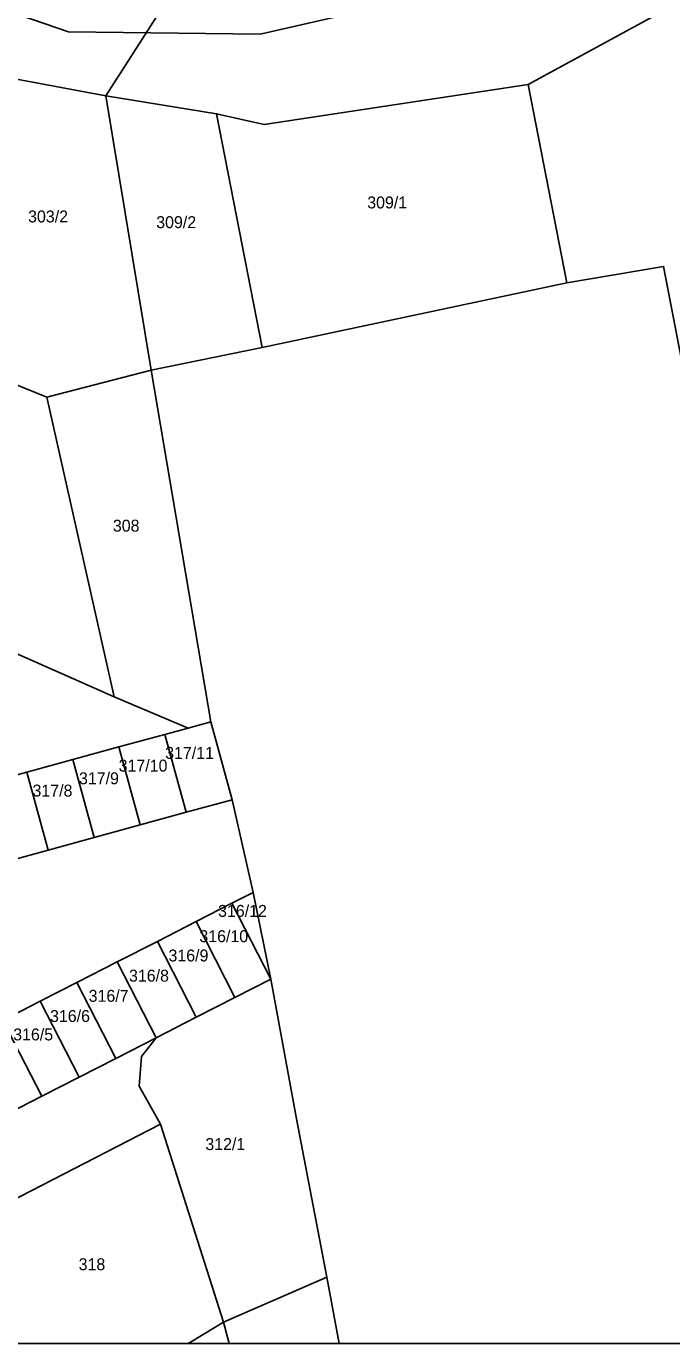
# Model space of a CAD drawing. Extents: x -873642 to -872917, y -1012962 to -1012567.
# Drawn here: x -873527.3 to -873481.3, y -1012961.7 to -1012867.8 of the extents above; entities that cross this region are included whole.
import ezdxf

# ---------------------------------------------------------------- set-up
doc = ezdxf.new("R2010")
doc.units = 0
for name, color, linetype in [('cisla_parcelni_kn', 7, 'Continuous'), ('osy_ulic', 7, 'Continuous'), ('parcely_kn', 7, 'Continuous'), ('stavebni_objekty_ostatni', 7, 'Continuous')]:
    doc.layers.add(name, color=color, linetype=linetype)

msp = doc.modelspace()

# ---------------------------------------------------------------- linework, layer by layer
at = {"layer": 'osy_ulic'}
msp.add_lwpolyline([(-873411.85, -1012822.53), (-873495.73, -1012864.97), (-873510.64, -1012868.38), (-873524.3, -1012868.21), (-873541.44, -1012862.33)], dxfattribs=at)
at = {"layer": 'parcely_kn'}
for p, q in [((-873528.799, -1012961.688), (-873515.787, -1012961.688)), ((-873528.799, -1012961.688), (-873515.787, -1012961.688)), ((-873515.787, -1012961.688), (-873512.858, -1012961.688)), ((-873515.787, -1012961.688), (-873512.858, -1012961.688)), ((-873512.858, -1012961.688), (-873505.023, -1012961.688)), ((-873512.858, -1012961.688), (-873505.023, -1012961.688)), ((-873505.023, -1012961.688), (-873433.111, -1012961.688)), ((-873505.023, -1012961.688), (-873433.111, -1012961.688))]:
    msp.add_line(p, q, dxfattribs=at)
for points in [[(-873407.44, -1012826.19), (-873491.56, -1012871.97), (-873510.35, -1012874.83), (-873513.75, -1012874.06), (-873521.64, -1012872.77), (-873517.87, -1012866.9), (-873506.6, -1012864.53), (-873501.14, -1012863.39), (-873495.55, -1012861.22), (-873491.75, -1012859.41), (-873424.19, -1012825.53), (-873422.58, -1012824.33), (-873421.37, -1012822.77), (-873420.24, -1012820.89), (-873420.07, -1012818.95), (-873420.2, -1012816.99), (-873420.81, -1012815.05)], [(-873407.44, -1012826.19), (-873491.56, -1012871.97), (-873510.35, -1012874.83), (-873513.75, -1012874.06), (-873521.64, -1012872.77), (-873517.87, -1012866.9), (-873506.6, -1012864.53), (-873501.14, -1012863.39), (-873495.55, -1012861.22), (-873491.75, -1012859.41), (-873424.19, -1012825.53), (-873422.58, -1012824.33), (-873421.37, -1012822.77), (-873420.24, -1012820.89), (-873420.07, -1012818.95), (-873420.2, -1012816.99), (-873420.81, -1012815.05)], [(-873518.4, -1012892.32), (-873525.83, -1012894.25), (-873533.05, -1012891.32), (-873548.33, -1012885.12), (-873544.35, -1012876.78), (-873540.91, -1012872.09), (-873537.72, -1012870.46), (-873532.98, -1012870.67), (-873521.64, -1012872.77)], [(-873518.4, -1012892.32), (-873525.83, -1012894.25), (-873533.05, -1012891.32), (-873548.33, -1012885.12), (-873544.35, -1012876.78), (-873540.91, -1012872.09), (-873537.72, -1012870.46), (-873532.98, -1012870.67), (-873521.64, -1012872.77)], [(-873513.75, -1012874.06), (-873510.35, -1012874.83), (-873491.56, -1012871.97), (-873488.8, -1012886.1), (-873510.5, -1012890.72)], [(-873513.75, -1012874.06), (-873510.35, -1012874.83), (-873491.56, -1012871.97), (-873488.8, -1012886.1), (-873510.5, -1012890.72)], [(-873510.5, -1012890.72), (-873518.4, -1012892.32), (-873521.64, -1012872.77), (-873513.75, -1012874.06)], [(-873510.5, -1012890.72), (-873518.4, -1012892.32), (-873521.64, -1012872.77), (-873513.75, -1012874.06)], [(-873533.05, -1012891.32), (-873525.83, -1012894.25), (-873521.05, -1012915.61), (-873532.64, -1012910.47), (-873539.95, -1012907.22)], [(-873533.05, -1012891.32), (-873525.83, -1012894.25), (-873521.05, -1012915.61), (-873532.64, -1012910.47), (-873539.95, -1012907.22)], [(-873518.4, -1012892.32), (-873514.15, -1012917.38), (-873515.78, -1012917.83), (-873521.05, -1012915.61), (-873525.83, -1012894.25)], [(-873518.4, -1012892.32), (-873514.15, -1012917.38), (-873515.78, -1012917.83), (-873521.05, -1012915.61), (-873525.83, -1012894.25)], [(-873517.43, -1012918.28), (-873515.78, -1012917.83), (-873514.15, -1012917.38), (-873512.63, -1012922.93), (-873515.91, -1012923.83)], [(-873517.43, -1012918.28), (-873515.78, -1012917.83), (-873514.15, -1012917.38), (-873512.63, -1012922.93), (-873515.91, -1012923.83)], [(-873520.71, -1012919.17), (-873517.43, -1012918.28), (-873515.91, -1012923.83), (-873519.19, -1012924.73)], [(-873520.71, -1012919.17), (-873517.43, -1012918.28), (-873515.91, -1012923.83), (-873519.19, -1012924.73)], [(-873523.99, -1012920.07), (-873520.71, -1012919.17), (-873519.19, -1012924.73), (-873522.47, -1012925.63)], [(-873523.99, -1012920.07), (-873520.71, -1012919.17), (-873519.19, -1012924.73), (-873522.47, -1012925.63)], [(-873527.27, -1012920.96), (-873523.99, -1012920.07), (-873522.47, -1012925.63), (-873525.75, -1012926.52)], [(-873527.27, -1012920.96), (-873523.99, -1012920.07), (-873522.47, -1012925.63), (-873525.75, -1012926.52)], [(-873530.55, -1012921.86), (-873527.27, -1012920.96), (-873525.75, -1012926.52), (-873529.03, -1012927.43)], [(-873530.55, -1012921.86), (-873527.27, -1012920.96), (-873525.75, -1012926.52), (-873529.03, -1012927.43)], [(-873512.65, -1012930.31), (-873511.15, -1012929.54), (-873509.89, -1012935.71)], [(-873512.65, -1012930.31), (-873511.15, -1012929.54), (-873509.89, -1012935.71)], [(-873512.65, -1012930.31), (-873509.89, -1012935.71), (-873512.45, -1012937.02), (-873515.21, -1012931.62)], [(-873512.65, -1012930.31), (-873509.89, -1012935.71), (-873512.45, -1012937.02), (-873515.21, -1012931.62)], [(-873512.45, -1012937.02), (-873515.2, -1012938.43), (-873517.96, -1012933.03), (-873515.21, -1012931.62)], [(-873512.45, -1012937.02), (-873515.2, -1012938.43), (-873517.96, -1012933.03), (-873515.21, -1012931.62)], [(-873515.2, -1012938.43), (-873518.06, -1012939.89), (-873520.82, -1012934.49), (-873517.96, -1012933.03)], [(-873515.2, -1012938.43), (-873518.06, -1012939.89), (-873520.82, -1012934.49), (-873517.96, -1012933.03)], [(-873518.06, -1012939.89), (-873520.92, -1012941.36), (-873523.69, -1012935.96), (-873520.82, -1012934.49)], [(-873518.06, -1012939.89), (-873520.92, -1012941.36), (-873523.69, -1012935.96), (-873520.82, -1012934.49)], [(-873520.92, -1012941.36), (-873523.53, -1012942.7), (-873526.3, -1012937.29), (-873523.69, -1012935.96)], [(-873520.92, -1012941.36), (-873523.53, -1012942.7), (-873526.3, -1012937.29), (-873523.69, -1012935.96)], [(-873512.45, -1012937.02), (-873509.89, -1012935.71), (-873508.05, -1012945.66), (-873505.9, -1012956.95), (-873513.26, -1012960.15), (-873517.74, -1012946.06), (-873519.25, -1012943.34), (-873519.1, -1012941.22), (-873518.06, -1012939.89), (-873515.2, -1012938.43)], [(-873512.45, -1012937.02), (-873509.89, -1012935.71), (-873508.05, -1012945.66), (-873505.9, -1012956.95), (-873513.26, -1012960.15), (-873517.74, -1012946.06), (-873519.25, -1012943.34), (-873519.1, -1012941.22), (-873518.06, -1012939.89), (-873515.2, -1012938.43)], [(-873523.53, -1012942.7), (-873526.2, -1012944.06), (-873528.97, -1012938.66), (-873526.3, -1012937.29)], [(-873523.53, -1012942.7), (-873526.2, -1012944.06), (-873528.97, -1012938.66), (-873526.3, -1012937.29)], [(-873526.2, -1012944.06), (-873529.35, -1012945.67), (-873532.12, -1012940.27), (-873528.97, -1012938.66)], [(-873526.2, -1012944.06), (-873529.35, -1012945.67), (-873532.12, -1012940.27), (-873528.97, -1012938.66)]]:
    msp.add_lwpolyline(points, close=True, dxfattribs=at)
for points in [[(-873478.14, -1012904.47), (-873481.91, -1012884.93), (-873488.8, -1012886.1), (-873491.56, -1012871.97), (-873407.44, -1012826.19)], [(-873478.14, -1012904.47), (-873481.91, -1012884.93), (-873488.8, -1012886.1), (-873491.56, -1012871.97), (-873407.44, -1012826.19)], [(-873517.87, -1012866.9), (-873521.64, -1012872.77), (-873532.98, -1012870.67), (-873537.72, -1012870.46), (-873540.91, -1012872.09), (-873544.35, -1012876.78), (-873548.33, -1012885.12), (-873555.3, -1012899.73), (-873557.88, -1012905.5), (-873562.72, -1012916.35), (-873568.64, -1012927.87), (-873575.25, -1012916.26), (-873572.63, -1012915.54), (-873569.39, -1012912.59), (-873566.07, -1012907.3), (-873563.74, -1012902.37), (-873561.65, -1012897.95), (-873551, -1012874.56), (-873549.72, -1012871.54), (-873539.71, -1012847.87)], [(-873517.87, -1012866.9), (-873521.64, -1012872.77), (-873532.98, -1012870.67), (-873537.72, -1012870.46), (-873540.91, -1012872.09), (-873544.35, -1012876.78), (-873548.33, -1012885.12), (-873555.3, -1012899.73), (-873557.88, -1012905.5), (-873562.72, -1012916.35), (-873568.64, -1012927.87), (-873575.25, -1012916.26), (-873572.63, -1012915.54), (-873569.39, -1012912.59), (-873566.07, -1012907.3), (-873563.74, -1012902.37), (-873561.65, -1012897.95), (-873551, -1012874.56), (-873549.72, -1012871.54), (-873539.71, -1012847.87)], [(-873433.111, -1012961.688), (-873435.72, -1012947.37), (-873445.76, -1012897.62), (-873478.14, -1012904.47), (-873481.91, -1012884.93), (-873488.8, -1012886.1), (-873510.5, -1012890.72), (-873518.4, -1012892.32), (-873514.15, -1012917.38), (-873512.63, -1012922.93), (-873511.15, -1012929.54), (-873509.89, -1012935.71), (-873508.05, -1012945.66), (-873505.9, -1012956.95), (-873505.023, -1012961.688)], [(-873433.111, -1012961.688), (-873435.72, -1012947.37), (-873445.76, -1012897.62), (-873478.14, -1012904.47), (-873481.91, -1012884.93), (-873488.8, -1012886.1), (-873510.5, -1012890.72), (-873518.4, -1012892.32), (-873514.15, -1012917.38), (-873512.63, -1012922.93), (-873511.15, -1012929.54), (-873509.89, -1012935.71), (-873508.05, -1012945.66), (-873505.9, -1012956.95), (-873505.023, -1012961.688)], [(-873532.64, -1012910.47), (-873521.05, -1012915.61), (-873515.78, -1012917.83), (-873517.43, -1012918.28), (-873520.71, -1012919.17), (-873523.99, -1012920.07), (-873527.27, -1012920.96), (-873530.55, -1012921.86)], [(-873532.64, -1012910.47), (-873521.05, -1012915.61), (-873515.78, -1012917.83), (-873517.43, -1012918.28), (-873520.71, -1012919.17), (-873523.99, -1012920.07), (-873527.27, -1012920.96), (-873530.55, -1012921.86)], [(-873529.03, -1012927.43), (-873525.75, -1012926.52), (-873522.47, -1012925.63), (-873519.19, -1012924.73), (-873515.91, -1012923.83), (-873512.63, -1012922.93), (-873511.15, -1012929.54), (-873512.65, -1012930.31), (-873515.21, -1012931.62), (-873517.96, -1012933.03), (-873520.82, -1012934.49), (-873523.69, -1012935.96), (-873526.3, -1012937.29), (-873528.97, -1012938.66)], [(-873529.03, -1012927.43), (-873525.75, -1012926.52), (-873522.47, -1012925.63), (-873519.19, -1012924.73), (-873515.91, -1012923.83), (-873512.63, -1012922.93), (-873511.15, -1012929.54), (-873512.65, -1012930.31), (-873515.21, -1012931.62), (-873517.96, -1012933.03), (-873520.82, -1012934.49), (-873523.69, -1012935.96), (-873526.3, -1012937.29), (-873528.97, -1012938.66)], [(-873528.799, -1012961.688), (-873531.64, -1012954.88), (-873530.07, -1012952.39), (-873517.74, -1012946.06), (-873519.25, -1012943.34), (-873519.1, -1012941.22), (-873518.06, -1012939.89), (-873520.92, -1012941.36), (-873523.53, -1012942.7), (-873526.2, -1012944.06), (-873529.35, -1012945.67), (-873532.49, -1012947.28), (-873531.49, -1012949.24), (-873546.7, -1012957.04), (-873545.68, -1012959.04), (-873550.1, -1012961.42), (-873550.179, -1012961.688)], [(-873528.799, -1012961.688), (-873531.64, -1012954.88), (-873530.07, -1012952.39), (-873517.74, -1012946.06), (-873519.25, -1012943.34), (-873519.1, -1012941.22), (-873518.06, -1012939.89), (-873520.92, -1012941.36), (-873523.53, -1012942.7), (-873526.2, -1012944.06), (-873529.35, -1012945.67), (-873532.49, -1012947.28), (-873531.49, -1012949.24), (-873546.7, -1012957.04), (-873545.68, -1012959.04), (-873550.1, -1012961.42), (-873550.179, -1012961.688)], [(-873515.787, -1012961.688), (-873515.6, -1012961.58), (-873513.26, -1012960.15), (-873517.74, -1012946.06), (-873530.07, -1012952.39), (-873531.64, -1012954.88), (-873528.799, -1012961.688)], [(-873515.787, -1012961.688), (-873515.6, -1012961.58), (-873513.26, -1012960.15), (-873517.74, -1012946.06), (-873530.07, -1012952.39), (-873531.64, -1012954.88), (-873528.799, -1012961.688)], [(-873505.023, -1012961.688), (-873505.9, -1012956.95), (-873513.26, -1012960.15), (-873512.858, -1012961.688)], [(-873505.023, -1012961.688), (-873505.9, -1012956.95), (-873513.26, -1012960.15), (-873512.858, -1012961.688)], [(-873512.858, -1012961.688), (-873513.26, -1012960.15), (-873515.6, -1012961.58), (-873515.787, -1012961.688)], [(-873512.858, -1012961.688), (-873513.26, -1012960.15), (-873515.6, -1012961.58), (-873515.787, -1012961.688)]]:
    msp.add_lwpolyline(points, dxfattribs=at)
at = {"layer": 'stavebni_objekty_ostatni'}
for points in [[(-873512.63, -1012922.93), (-873515.91, -1012923.83), (-873517.43, -1012918.28), (-873515.78, -1012917.83), (-873514.15, -1012917.38)], [(-873520.71, -1012919.17), (-873517.43, -1012918.28), (-873515.91, -1012923.83), (-873519.19, -1012924.73)], [(-873520.71, -1012919.17), (-873519.19, -1012924.73), (-873522.47, -1012925.63), (-873523.99, -1012920.07)], [(-873527.27, -1012920.96), (-873523.99, -1012920.07), (-873522.47, -1012925.63), (-873525.75, -1012926.52)], [(-873530.55, -1012921.86), (-873527.27, -1012920.96), (-873525.75, -1012926.52), (-873529.03, -1012927.43)], [(-873512.65, -1012930.31), (-873509.89, -1012935.71), (-873512.45, -1012937.02), (-873515.21, -1012931.62)], [(-873517.96, -1012933.03), (-873515.21, -1012931.62), (-873512.45, -1012937.02), (-873515.2, -1012938.43)], [(-873518.06, -1012939.89), (-873520.82, -1012934.49), (-873517.96, -1012933.03), (-873515.2, -1012938.43)], [(-873518.06, -1012939.89), (-873520.92, -1012941.36), (-873523.69, -1012935.96), (-873520.82, -1012934.49)], [(-873523.53, -1012942.7), (-873526.3, -1012937.29), (-873523.69, -1012935.96), (-873520.92, -1012941.36)], [(-873526.2, -1012944.06), (-873528.97, -1012938.66), (-873526.3, -1012937.29), (-873523.53, -1012942.7)], [(-873529.35, -1012945.67), (-873532.12, -1012940.27), (-873528.97, -1012938.66), (-873526.2, -1012944.06)]]:
    msp.add_lwpolyline(points, close=True, dxfattribs=at)

# ---------------------------------------------------------------- texts
at = {"layer": 'cisla_parcelni_kn'}
for s, p in [('309/1', (-873503.015, -1012880.8)), ('309/1', (-873503.015, -1012880.8)), ('303/2', (-873527.171, -1012881.8)), ('303/2', (-873527.171, -1012881.8)), ('309/2', (-873518.046, -1012882.206)), ('309/2', (-873518.046, -1012882.206)), ('308', (-873521.133, -1012903.831)), ('308', (-873521.133, -1012903.831)), ('317/11', (-873517.408, -1012920.019)), ('317/11', (-873517.408, -1012920.019)), ('317/10', (-873520.721, -1012920.925)), ('317/10', (-873520.721, -1012920.925)), ('317/9', (-873523.546, -1012921.831)), ('317/9', (-873523.546, -1012921.831)), ('317/8', (-873526.858, -1012922.706)), ('317/8', (-873526.858, -1012922.706)), ('316/12', (-873513.638, -1012931.278)), ('316/12', (-873513.638, -1012931.278)), ('316/10', (-873514.971, -1012933.081)), ('316/10', (-873514.971, -1012933.081)), ('316/9', (-873517.171, -1012934.456)), ('316/9', (-873517.171, -1012934.456)), ('316/8', (-873519.983, -1012935.894)), ('316/8', (-873519.983, -1012935.894)), ('316/7', (-873522.858, -1012937.331)), ('316/7', (-873522.858, -1012937.331)), ('316/6', (-873525.608, -1012938.769)), ('316/6', (-873525.608, -1012938.769)), ('316/5', (-873528.233, -1012940.081)), ('316/5', (-873528.233, -1012940.081)), ('312/1', (-873514.546, -1012947.894)), ('312/1', (-873514.546, -1012947.894)), ('318', (-873523.571, -1012956.456)), ('318', (-873523.571, -1012956.456))]:
    msp.add_text(s, height=0.85, dxfattribs=at).set_placement(p)

doc.saveas('drawing.dxf')
